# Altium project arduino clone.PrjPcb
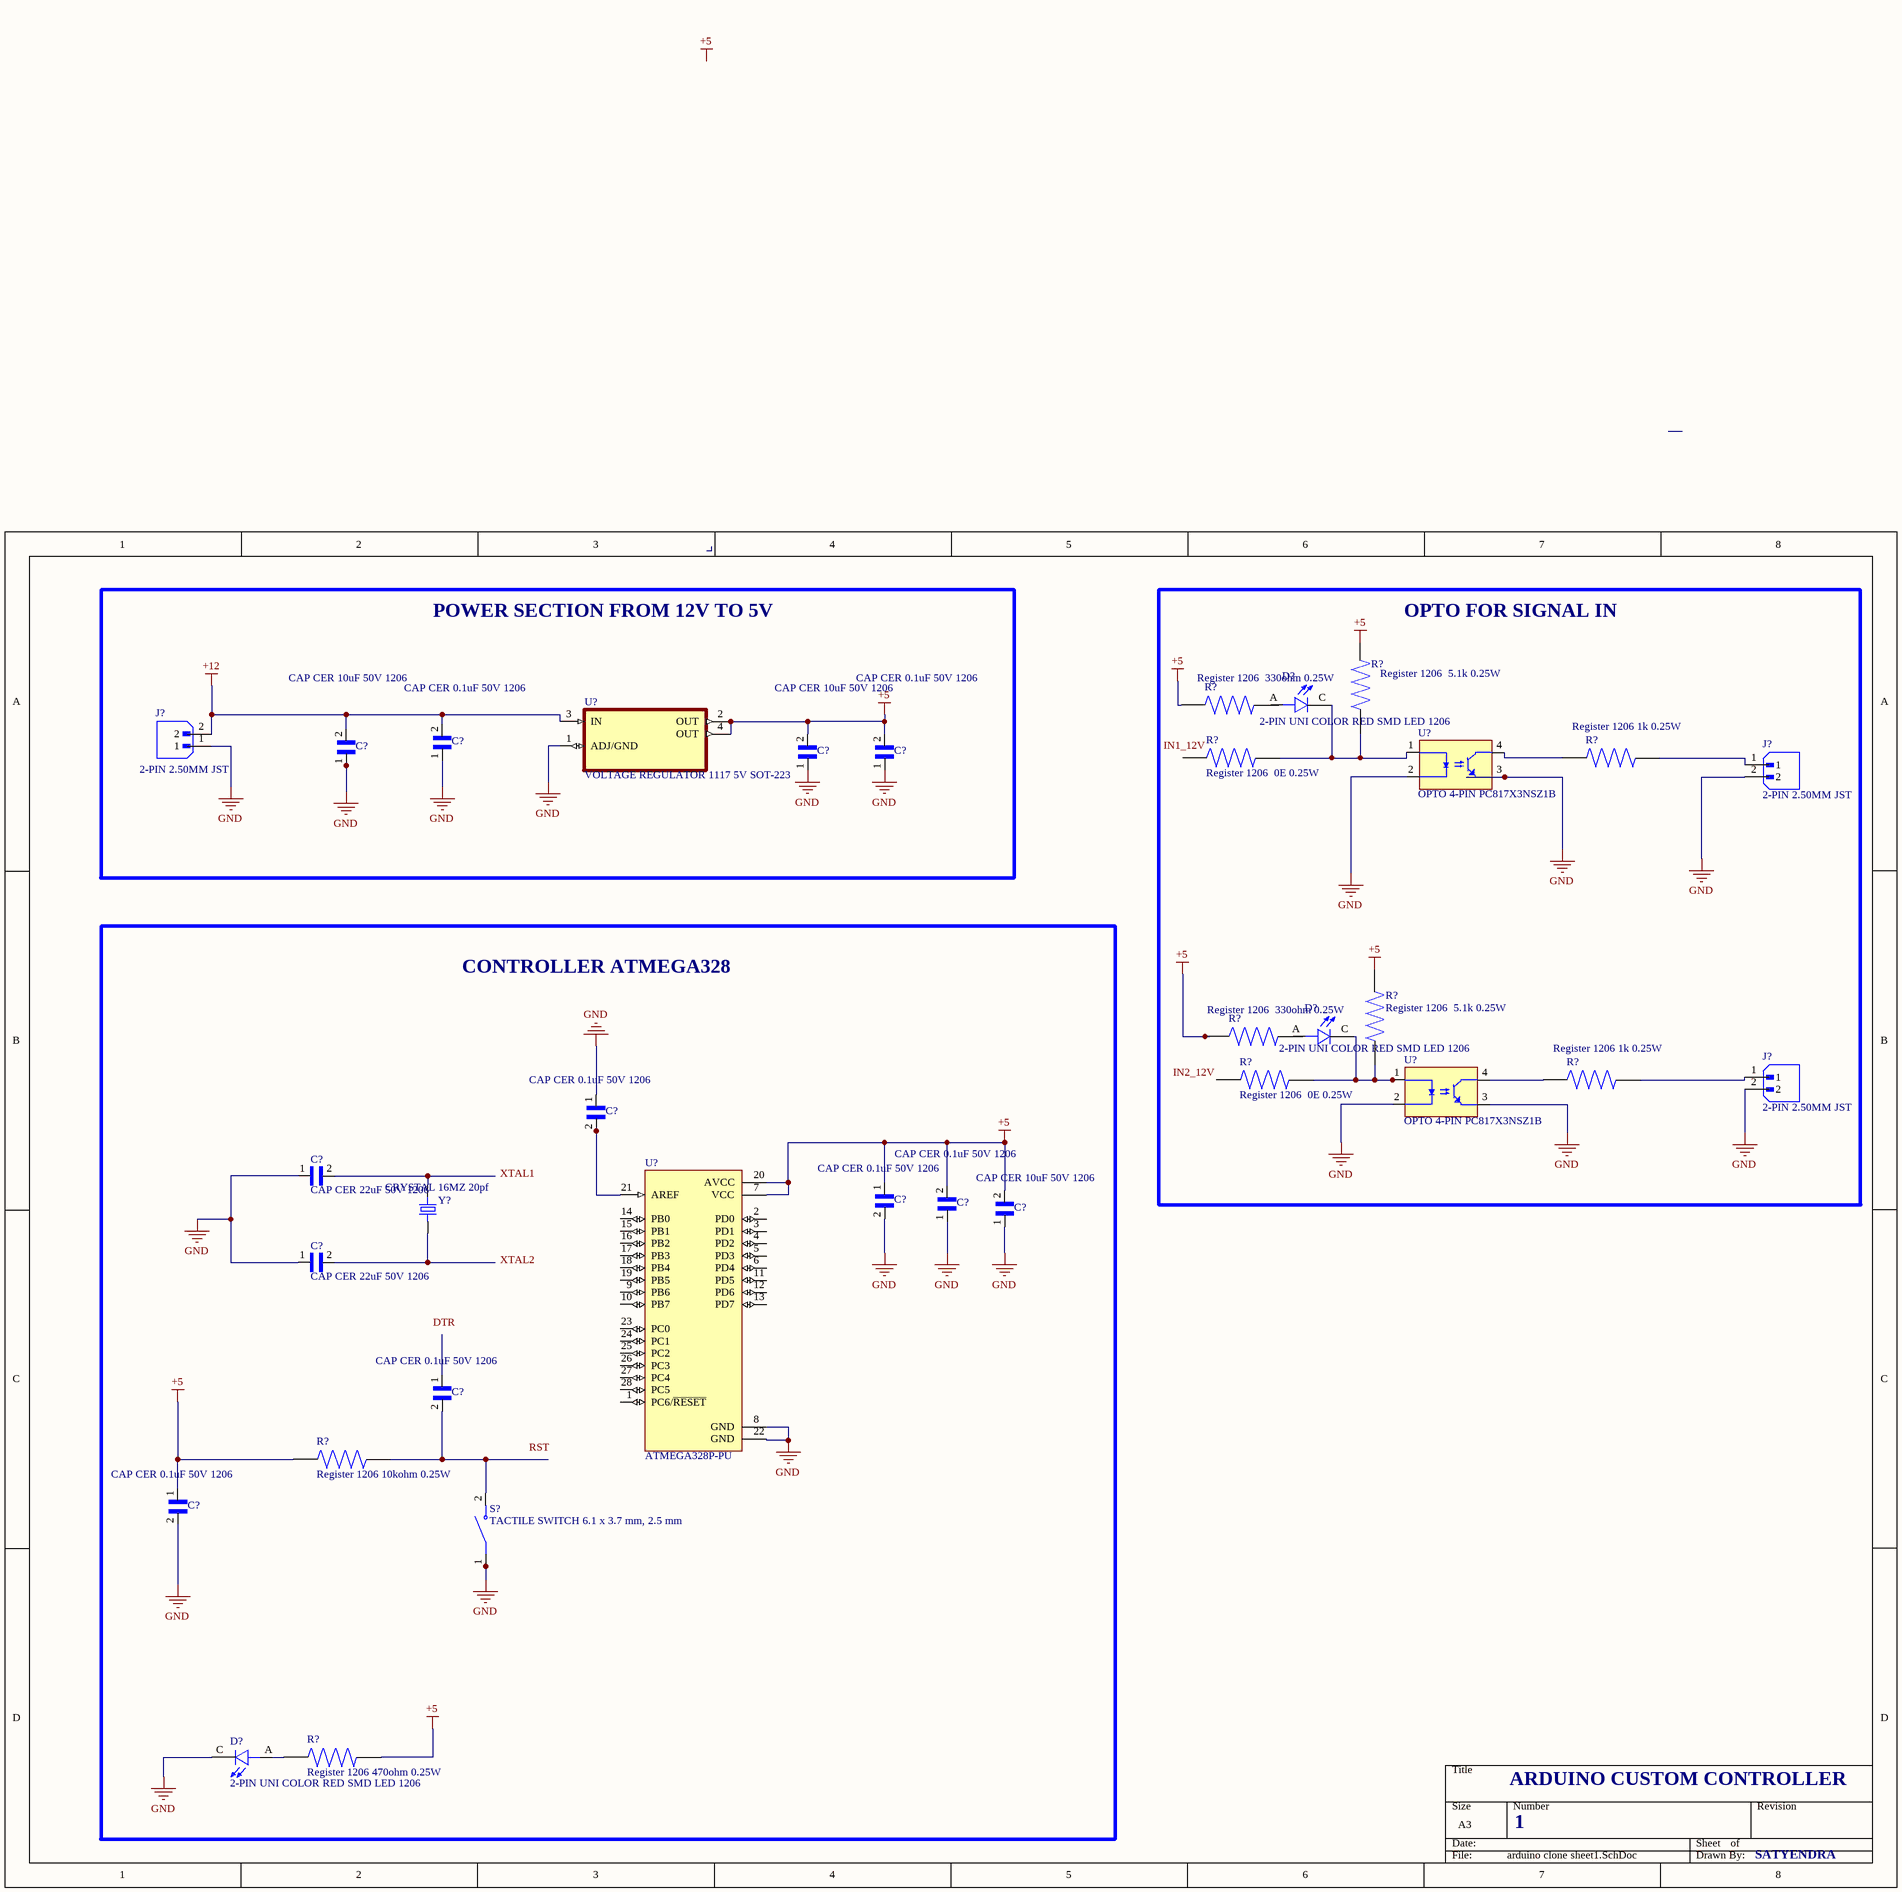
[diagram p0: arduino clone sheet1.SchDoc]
2 sheets, 37 parts. Net scope: global (net labels, ports and power ports of the same name join across sheets).
Board file: arduino clone PCB.PcbDoc
Sheets:
  arduino clone sheet1.SchDoc
  arduino clone sheet2.SchDoc

## Sheet arduino clone sheet1.SchDoc
size A3; SheetNumber: 1; SheetTotal: 2

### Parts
(Parts that share a designator on the sheet are numbered #1, #2 ... from top to bottom, then left to right.)
C?#1  CAP CER 0.1uF 50V 1206  [capacitor 100nF 1206]
C?#2  CAP CER 10uF 50V 1206  [capacitor 100nF 1206]
C?#3  CAP CER 10uF 50V 1206  [capacitor 100nF 1206]
C?#4  CAP CER 0.1uF 50V 1206  [capacitor 100nF 1206]
C?#5  CAP CER 0.1uF 50V 1206  [capacitor 100nF 1206]
C?#6  CAP CER 22uF 50V 1206  [capacitor 100nF 1206]
C?#7  CAP CER 0.1uF 50V 1206  [capacitor 100nF 1206]
C?#8  CAP CER 0.1uF 50V 1206  [capacitor 100nF 1206]
C?#9  CAP CER 10uF 50V 1206  [capacitor 100nF 1206]
C?#10  CAP CER 22uF 50V 1206  [capacitor 100nF 1206]
C?#11  CAP CER 0.1uF 50V 1206  [capacitor 100nF 1206]
C?#12  CAP CER 0.1uF 50V 1206  [capacitor 100nF 1206]
D?#1  2-PIN UNI COLOR RED SMD LED 1206  [2-PIN UNI COLOR RED SMD LED 1206]
D?#2  2-PIN UNI COLOR RED SMD LED 1206  [2-PIN UNI COLOR RED SMD LED 1206]
D?#3  2-PIN UNI COLOR RED SMD LED 1206  [2-PIN UNI COLOR RED SMD LED 1206]
J?#1  2-PIN 2.50MM JST  [2-PIN 2.50MM JST]
J?#2  2-PIN 2.50MM JST  [2-PIN 2.50MM JST]
J?#3  2-PIN 2.50MM JST  [2-PIN 2.50MM JST]
R?#1  Register 1206  5.1k 0.25W  [Register 1206 10kohm]
R?#2  Register 1206  330ohm 0.25W  [Register 1206 10kohm]
R?#3  Register 1206  0E 0.25W  [Register 1206 10kohm]
R?#4  Register 1206 1k 0.25W  [Register 1206 10kohm]
R?#5  Register 1206  5.1k 0.25W  [Register 1206 10kohm]
R?#6  Register 1206  330ohm 0.25W  [Register 1206 10kohm]
R?#7  Register 1206  0E 0.25W  [Register 1206 10kohm]
R?#8  Register 1206 1k 0.25W  [Register 1206 10kohm]
R?#9  Register 1206 10kohm 0.25W  [Register 1206 10kohm]
R?#10  Register 1206 470ohm 0.25W  [Register 1206 10kohm]
S?  TACTILE SWITCH 6.1 x 3.7 mm, 2.5 mm  [TACTILE SWITCH 6.1 x 3.7 mm, 2.5 mm]
U?#1  VOLTAGE REGULATOR 1117 5V SOT-223  [VOLTAGE REGULATOR 1117 5V SOT-223]
U?#2  OPTO 4-PIN PC817X3NSZ1B  [OPTO 4-PIN PC817X3NSZ1B]
U?#3  OPTO 4-PIN PC817X3NSZ1B  [OPTO 4-PIN PC817X3NSZ1B]
U?#4  ATMEGA328P-PU  [Atmega328pU DIP Controller]
Y?  CRYSTAL 16MZ 20pf  [CRYSTAL 16MZ 20pf]

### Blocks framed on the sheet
POWER SECTION FROM 12V TO 5V: C?#1-C?#4 J?#1 U?#1
OPTO FOR SIGNAL IN: D?#1 D?#2 J?#2 J?#3 R?#1-R?#8 U?#2 U?#3
CONTROLLER ATMEGA328: C?#5-C?#12 D?#3 R?#9 R?#10 S? U?#4 Y?

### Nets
+5: C?#3.2 C?#4.2 C?#7.1 C?#8.2 C?#9.2 C?#12.1 R?#2.1 R?#6.1 R?#9.1 R?#10.2 U?#1.2(OUT) U?#1.4(OUT) U?#4.7(VCC) U?#4.20(AVCC)
+12: C?#1.2 C?#2.2 J?#1.2 U?#1.3(IN)
GND: C?#1.1 C?#2.1 C?#3.1 C?#4.1 C?#5.1 C?#6.1 C?#7.2 C?#8.1 C?#9.1 C?#10.1 C?#12.2 D?#3.C J?#1.1 J?#2.2 J?#3.2 S?.1 U?#1.1(ADJ/GND) U?#2.2(CATHODE) U?#2.3(EMITTER) U?#3.2(CATHODE) U?#3.3(EMITTER) U?#4.8(GND) U?#4.22(GND)
NetC?#5_2: C?#5.2 U?#4.21(AREF)
NetC?#6_2: C?#6.2 Y?.2
NetC?#10_2: C?#10.2 Y?.1
NetC?#11_2: C?#11.2 R?#9.2 S?.2
NetD?#1_C: D?#1.C R?#1.1 R?#3.2 U?#2.1(ANODE)
NetD?#2_C: D?#2.C R?#5.1 R?#7.2 U?#3.1(ANODE)
NetD?#3_A: D?#3.A R?#10.1
NetJ?#2_1: J?#2.1 R?#4.2
NetJ?#3_1: J?#3.1 R?#8.2
NetR?#4_1: R?#4.1 U?#2.4(COLLECTOR)
NetR?#8_1: R?#8.1 U?#3.4(COLLECTOR)

Not connected (* = marked no-connect by the designer): C?#11 1; D?#1 A; D?#2 A; R?#1 2; R?#2 2; R?#3 1; R?#5 2; R?#6 2; R?#7 1; U?#4 1(PC6/~{RESET}) 2(PD0) 3(PD1) 4(PD2) 5(PD3) 6(PD4) 9(PB6) 10(PB7) 11(PD5) 12(PD6) 13(PD7) 14(PB0) 15(PB1) 16(PB2) 17(PB3) 18(PB4) 19(PB5) 23(PC0) 24(PC1) 25(PC2) 26(PC3) 27(PC4) 28(PC5)

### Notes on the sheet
- ARDUINO CUSTOM CONTROLLER
- 1
- SATYENDRA
- Labels drawn without touching a wire or pin: +5, DTR, IN1_12V, IN2_12V, RST, XTAL1, XTAL2

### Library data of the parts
C?#1-C?#5 C?#7-C?#9 C?#11 C?#12 = CAP CER 10uF 50V 1206: C1206C101J2GACTU CAP CER 100PF 200V C0G/NP0 1206
C?#6 C?#10 = CAP CER 22uF 50V 1206: C1206C101J2GACTU CAP CER 100PF 200V C0G/NP0 1206
D?#1-D?#3 = 2-PIN UNI COLOR RED SMD LED 1206: LED Uni-Color Red 660nm 2-Pin SMD T/R; MP: BR1102W-TR
J?#1-J?#3 = 2-PIN 2.50MM JST: Connector Header Through Hole 2 position 0.098 (2.50mm); MF: JST Sales; MP: B2B-XH-A(LF)(SN)
R?#1 R?#5 = Register 1206 5.1k 0.25W: Register 1206 10kohm; MP: RNCF1206BKY10K0
R?#2 R?#6 = Register 1206 330ohm 0.25W: Register 1206 10kohm; MP: RNCF1206BKY10K0
R?#3 R?#7 = Register 1206 0E 0.25W: Register 1206 10kohm; MP: RNCF1206BKY10K0
R?#4 R?#8 = Register 1206 1k 0.25W: Register 1206 10kohm; MP: RNCF1206BKY10K0
R?#9 = Register 1206 10kohm 0.25W: Register 1206 10kohm; MP: RNCF1206BKY10K0
R?#10 = Register 1206 470ohm 0.25W: Register 1206 10kohm; MP: RNCF1206BKY10K0
S? = TACTILE SWITCH 6.1 x 3.7 mm, 2.5 mm: 6.1 x 3.7 mm, 2.5 mm Actuator Height, 260 gf, Red, Surface Mount, SPST, Tactile Switch TS09-63-25-R-260-SMT-TR; MF: Same Sky
U?#1 = VOLTAGE REGULATOR 1117 5V SOT-223: 800-mA, 15-V, linear voltage regulator 4-SOT-223 0 to 125 TLV1117-50CDCYRG3; MF: Texas Instruments
U?#2 U?#3 = OPTO 4-PIN PC817X3NSZ1B: Optoisolator Transistor Output - 1 Channel 4-DIP; MF: Sharp Microelectronics
U?#4 = ATMEGA328P-PU: ATmega Series 20 MHz 32 KB Flash 2 KB SRAM 8-Bit Microcontroller - DIP-28
Y? = CRYSTAL 16MZ 20pf: 16 MHz Â±30ppm Crystal 20pF 40 Ohms HC-49/US ECS-160-20-5PX-TR; MF: ECS Inc.

## Sheet arduino clone sheet2.SchDoc
size A; SheetNumber: 2; SheetTotal: 2
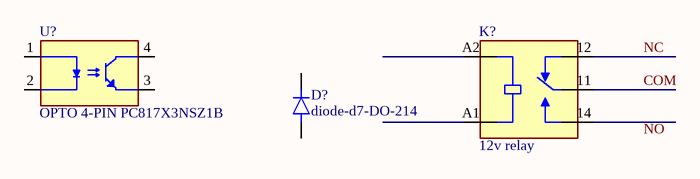
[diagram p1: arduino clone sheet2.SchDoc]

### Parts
(Parts that share a designator on the sheet are numbered #1, #2 ... from top to bottom, then left to right.)
D?#4  diode-d7-DO-214  [diode-d7-DO-214]
K?  12v relay  [RELAY_833H-1C-S-12VDC]
U?#5  OPTO 4-PIN PC817X3NSZ1B  [OPTO 4-PIN PC817X3NSZ1B]

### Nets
COM: K?.11(COM)
NC: K?.12(NC)

Not connected (* = marked no-connect by the designer): D?#4 A C; K? 14(NO) A1(COIL2) A2(COIL1); U?#5 1(ANODE) 2(CATHODE) 3(EMITTER) 4(COLLECTOR)

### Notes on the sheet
- Labels drawn without touching a wire or pin: NO

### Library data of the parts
D?#4 = diode-d7-DO-214: MF: Diodes Inc.; MP: S1M-13-F
K? = 833H-1C-S-12VDC: 833H Series 10 A SPDT 12 VDC Through Hole Miniature Sugar Cube Power Relay; MF: Song Chuan
U?#5 = OPTO 4-PIN PC817X3NSZ1B: as U?#2 on sheet arduino clone sheet1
